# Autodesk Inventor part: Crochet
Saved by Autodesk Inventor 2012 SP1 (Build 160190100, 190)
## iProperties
Created: 2014-12
Part Number: Crochet
Material: Default
Document SubType Name: Modeling
Designer: Bruno
Density: 1 g/cm^3
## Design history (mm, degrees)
node "Crochet1"
node "Crochet"
node "Base1"
